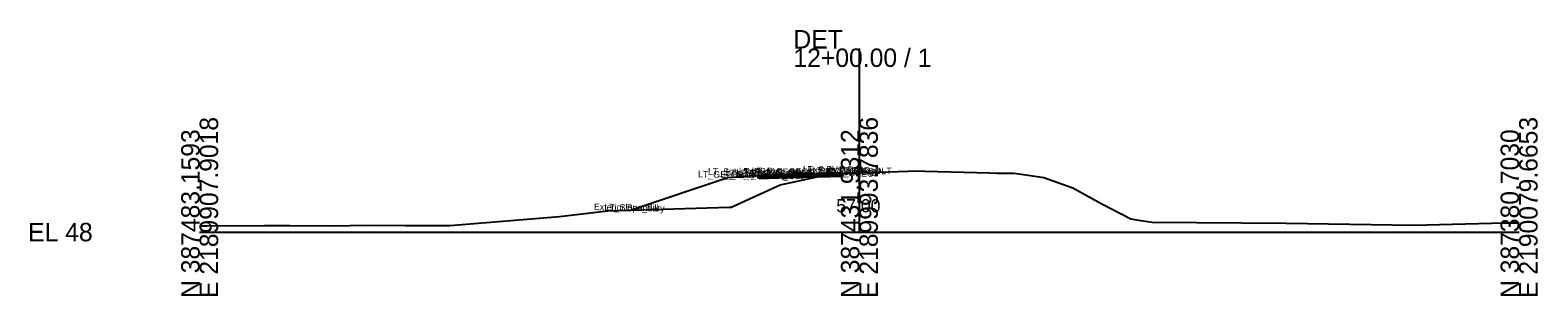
# Model space of a CAD drawing. Extents: x -26 to 1203, y -10 to 9543.
# Drawn here: x -25.7 to 202.8, y 1990.3 to 2030.7 of the extents above; entities that cross this region are included whole.
import ezdxf

# ---------------------------------------------------------------- set-up
doc = ezdxf.new("R2010")
doc.units = 0
for name, color, linetype in [('Default', 7, 'Continuous'), ('Exist Cross Section Cell', 7, 'Continuous'), ('Exist XS Center Line Elevation Label', 7, 'Continuous'), ('Exist XS Ground Line', 7, 'Continuous'), ('Prop CMT Pvmt Course 1', 7, 'Continuous'), ('Prop CMT Pvmt Course 2', 7, 'Continuous'), ('Prop CMT Pvmt Surface', 7, 'Continuous'), ('Prop CMT Pvmt Surface Shoulder', 7, 'Continuous'), ('Prop CMT Shld Paved Course 1', 7, 'Continuous'), ('Prop CMT Shld Paved Course 2', 7, 'Continuous'), ('Prop CMT Slope Grass', 7, 'Continuous'), ('Prop CMT Subgrade Earthwork', 7, 'Continuous'), ('Scratch_Level_0', 7, 'Continuous')]:
    doc.layers.add(name, color=color, linetype=linetype)

msp = doc.modelspace()

# ---------------------------------------------------------------- linework, layer by layer
at = {"layer": 'Exist Cross Section Cell'}
for p, q in [((100, 2000), (100, 2027.88)), ((0, 2000), (100, 2000)), ((100, 2000), (200, 2000))]:
    msp.add_line(p, q, dxfattribs=at)
at = {"layer": 'Exist XS Ground Line'}
for p, q in [((95.55, 2008.78), (95.91, 2008.85)), ((95.91, 2008.85), (97.48, 2008.91)), ((97.48, 2008.91), (100, 2009)), ((100, 2009), (107.33, 2009.25)), ((107.33, 2009.25), (108.61, 2009.29)), ((108.61, 2009.29), (109.9, 2009.25)), ((109.9, 2009.25), (119.78, 2009.01)), ((119.78, 2009.01), (120.95, 2008.96)), ((120.95, 2008.96), (121.26, 2008.95)), ((121.26, 2008.95), (121.78, 2008.95)), ((121.78, 2008.95), (123.45, 2008.93)), ((123.45, 2008.93), (125.56, 2008.63)), ((80.94, 2003.93), (88.01, 2007.18)), ((88.01, 2007.18), (94.13, 2008.48)), ((94.13, 2008.48), (95.55, 2008.78)), ((125.56, 2008.63), (127.96, 2008.3)), ((127.96, 2008.3), (130.09, 2007.54)), ((130.09, 2007.54), (132.37, 2006.73)), ((132.37, 2006.73), (136.75, 2004.31)), ((136.75, 2004.31), (141.15, 2002)), ((37.93, 2001.01), (54.52, 2002.35)), ((54.52, 2002.35), (61.82, 2003.21)), ((61.82, 2003.21), (80.25, 2003.76)), ((80.25, 2003.76), (80.6, 2003.78)), ((80.6, 2003.78), (80.94, 2003.93)), ((141.15, 2002), (142.68, 2001.74)), ((0, 2000.97), (1.11, 2000.97)), ((1.11, 2000.97), (9.84, 2001.02)), ((9.84, 2001.02), (11.89, 2001.02)), ((11.89, 2001.02), (13.68, 2001.02)), ((13.68, 2001.02), (19.67, 2000.95)), ((19.67, 2000.95), (25.85, 2001.05)), ((25.85, 2001.05), (31.18, 2000.99)), ((31.18, 2000.99), (37.93, 2001.01)), ((142.68, 2001.74), (144.39, 2001.52)), ((144.39, 2001.52), (164.68, 2001.34)), ((164.68, 2001.34), (183.97, 2001.04)), ((183.97, 2001.04), (197.8, 2001.38)), ((197.8, 2001.38), (200, 2001.41))]:
    msp.add_line(p, q, dxfattribs=at)
at = {"layer": 'Prop CMT Pvmt Course 1'}
for points in [[(97.48, 2009), (87.81, 2008.74)], [(97.48, 2008.75), (97.48, 2009)], [(87.81, 2008.49), (97.48, 2008.75)], [(87.81, 2008.74), (87.81, 2008.49)]]:
    msp.add_lwpolyline(points, dxfattribs=at)
at = {"layer": 'Prop CMT Pvmt Course 2'}
for points in [[(97.48, 2008.75), (87.81, 2008.49)], [(87.81, 2008.24), (97.48, 2008.5)], [(87.81, 2008.49), (87.81, 2008.24)], [(97.48, 2008.5), (97.48, 2008.75)]]:
    msp.add_lwpolyline(points, dxfattribs=at)
at = {"layer": 'Prop CMT Pvmt Surface'}
msp.add_lwpolyline([(97.48, 2009), (87.81, 2008.74)], dxfattribs=at)
at = {"layer": 'Prop CMT Pvmt Surface Shoulder'}
msp.add_lwpolyline([(87.81, 2008.74), (85.81, 2008.69)], dxfattribs=at)
at = {"layer": 'Prop CMT Shld Paved Course 1'}
for points in [[(87.81, 2008.74), (85.81, 2008.69), (85.55, 2008.43)], [(85.55, 2008.43), (87.81, 2008.49)], [(87.81, 2008.49), (87.81, 2008.74)]]:
    msp.add_lwpolyline(points, dxfattribs=at)
at = {"layer": 'Prop CMT Shld Paved Course 2'}
for points in [[(87.81, 2008.49), (85.55, 2008.43), (85.05, 2008.42), (84.8, 2008.16)], [(84.8, 2008.16), (87.81, 2008.24)], [(87.81, 2008.24), (87.81, 2008.49)]]:
    msp.add_lwpolyline(points, dxfattribs=at)
at = {"layer": 'Prop CMT Slope Grass'}
for points in [[(80.07, 2008.23), (65.1, 2003.23)], [(85.81, 2008.69), (80.07, 2008.23)]]:
    msp.add_lwpolyline(points, dxfattribs=at)
at = {"layer": 'Prop CMT Subgrade Earthwork'}
for points in [[(87.81, 2008.24), (97.48, 2008.5), (97.49, 2008.91)], [(84.8, 2008.16), (84.39, 2008.58)], [(87.81, 2008.24), (84.8, 2008.16)]]:
    msp.add_lwpolyline(points, dxfattribs=at)

# ---------------------------------------------------------------- texts
at = {"layer": 'Default'}
msp.add_text('-', height=0.0001, dxfattribs=at).set_placement((0, 2000))
at = {"layer": 'Exist Cross Section Cell'}
for s, p in [('DET', (90, 2027.88)), ('12+00.00 / 1', (90, 2025.08)), ('EL 48', (-26, 1998.6))]:
    msp.add_text(s, height=2.8, dxfattribs=at).set_placement(p)
for s, p in [('E 2189907.9018', (2.8, 1990)), ('E 2189993.7836', (102.8, 1990)), ('E 2190079.6653', (202.8, 1990)), ('N 387483.1593', (0, 1990)), ('N 387431.9312', (100, 1990)), ('N 387380.7030', (200, 1990))]:
    msp.add_text(s, height=2.8, rotation=90, dxfattribs=at).set_placement(p)
at = {"layer": 'Exist XS Center Line Elevation Label'}
msp.add_text('57.00', height=2, dxfattribs=at).set_placement((96.5, 2003))
at = {"layer": 'Scratch_Level_0'}
for s, p in [('LT_GS_OS_CTL', (75.53, 2008.32)), ('LT_Sub_Trench_Out_DLT', (77.04, 2008.72)), ('LT_Sub_Trench_Out', (78.91, 2008.28)), ('LT_PS2_Shelf_Out', (79.71, 2008.52)), ('LT_PS2_OEOP', (81.34, 2008.52)), ('LT_PS1_OEOP', (81.72, 2008.77)), ('LT_PV2_OEOT', (83.56, 2008.58)), ('LT_Sub_OEOT', (83.58, 2008.33)), ('LT_PV1_OEOT', (83.68, 2008.82)), ('LT_Sub_OEEOP_DLT', (91.44, 2009.03)), ('Exterior Boundary', (92.15, 2009.02)), ('LT_PV2_OEEOP', (92.87, 2008.84)), ('LT_Sub_OEEOP', (92.9, 2008.58)), ('PV1_PGL', (94.95, 2009.04)), ('Exterior Boundary', (59.76, 2003.34)), ('LT_Slope_Fill', (61.34, 2003.31))]:
    msp.add_text(s, height=1, rotation=358.8836, dxfattribs=at).set_placement(p)

doc.saveas('drawing.dxf')
